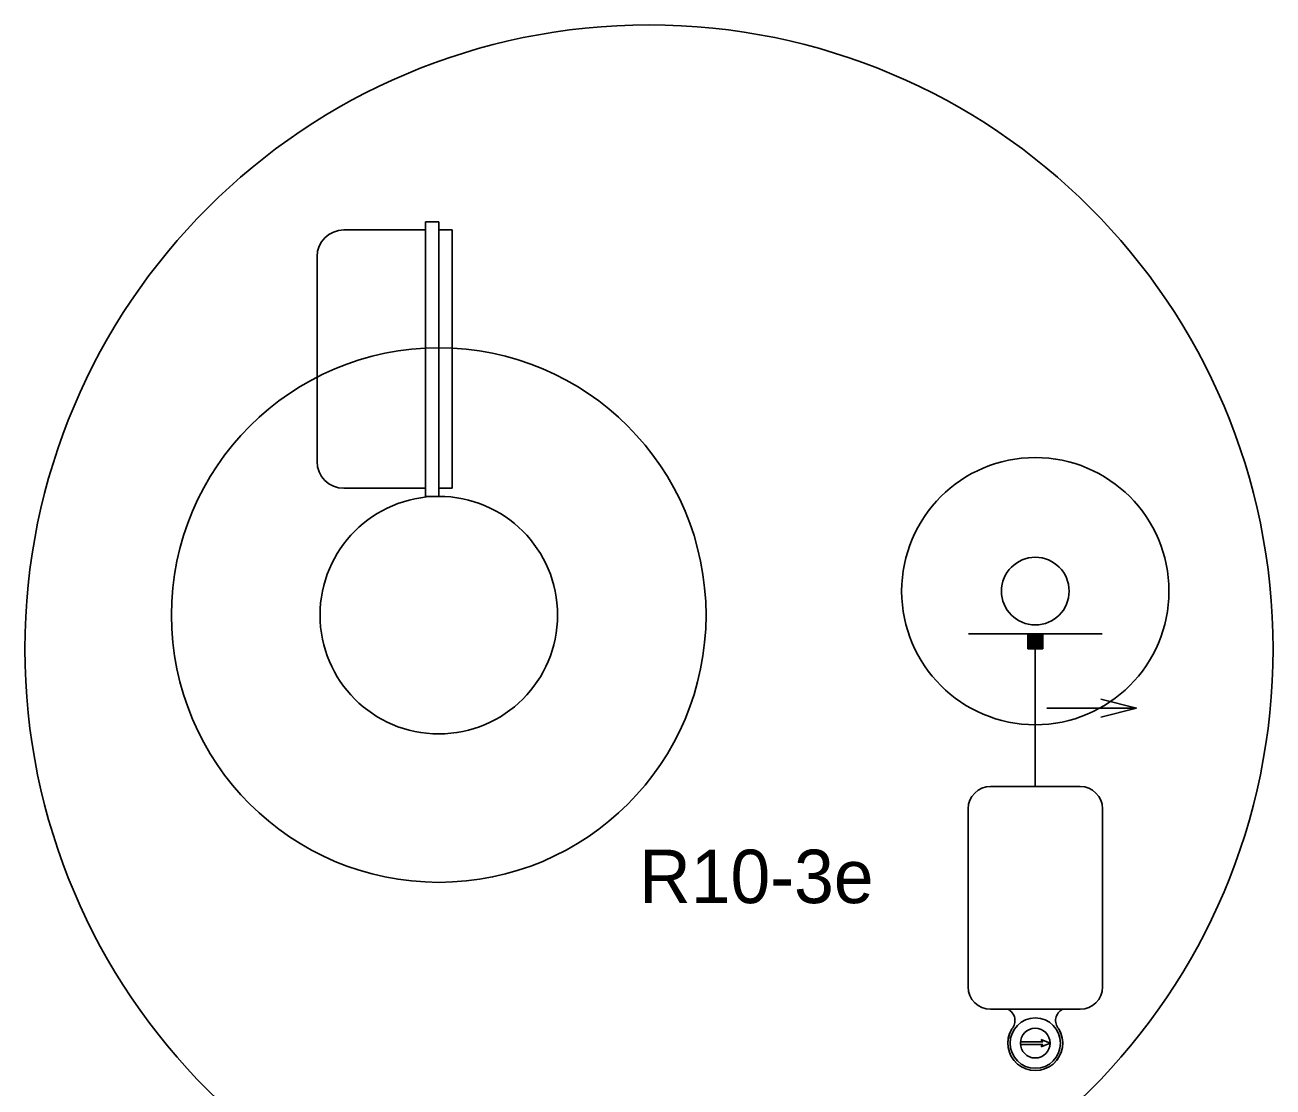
# Model space of a CAD drawing. Extents: x 1369885 to 1370886, y 379976 to 380616.
# Drawn here: x 1370504.6 to 1370609.7, y 380165.8 to 380255.2 of the extents above; entities that cross this region are included whole.
import ezdxf

# ---------------------------------------------------------------- set-up
doc = ezdxf.new("R2010")
doc.units = 0
doc.layers.add('T_Drafting', color=7, linetype='Continuous')

msp = doc.modelspace()

# ---------------------------------------------------------------- linework, layer by layer
at = {"layer": 'T_Drafting'}
for p, q in [((1370538.3, 380215.52), (1370538.3, 380238.64)), ((1370539.43, 380238.64), (1370538.3, 380238.64)), ((1370539.43, 380215.52), (1370539.43, 380238.64)), ((1370538.3, 380237.95), (1370531.43, 380237.95)), ((1370540.55, 380237.95), (1370539.43, 380237.95)), ((1370540.55, 380216.2), (1370540.55, 380237.95)), ((1370529.18, 380218.45), (1370529.18, 380235.7)), ((1370538.3, 380216.2), (1370531.43, 380216.2)), ((1370540.55, 380216.2), (1370539.43, 380216.2)), ((1370539.43, 380215.52), (1370538.3, 380215.52)), ((1370595.28, 380203.94), (1370584.03, 380203.94)), ((1370589.03, 380202.69), (1370589.03, 380203.94)), ((1370589.03, 380202.7), (1370590.27, 380203.94)), ((1370589.03, 380202.72), (1370590.25, 380203.94)), ((1370589.03, 380202.74), (1370590.23, 380203.94)), ((1370589.03, 380202.76), (1370590.21, 380203.94)), ((1370589.03, 380202.78), (1370590.18, 380203.94)), ((1370589.03, 380202.8), (1370590.16, 380203.94)), ((1370589.03, 380202.82), (1370590.14, 380203.94)), ((1370589.03, 380202.84), (1370590.12, 380203.94)), ((1370589.03, 380202.87), (1370590.1, 380203.94)), ((1370589.03, 380202.89), (1370590.08, 380203.94)), ((1370589.03, 380202.91), (1370590.06, 380203.94)), ((1370589.03, 380202.93), (1370590.04, 380203.94)), ((1370589.03, 380202.95), (1370590.01, 380203.94)), ((1370589.03, 380202.97), (1370589.99, 380203.94)), ((1370589.03, 380202.99), (1370589.97, 380203.94)), ((1370589.03, 380203.01), (1370589.95, 380203.94)), ((1370589.03, 380203.04), (1370589.93, 380203.94)), ((1370589.03, 380203.06), (1370589.91, 380203.94)), ((1370589.03, 380203.08), (1370589.89, 380203.94)), ((1370589.03, 380203.1), (1370589.87, 380203.94)), ((1370589.03, 380203.12), (1370589.84, 380203.94)), ((1370589.03, 380203.14), (1370589.82, 380203.94)), ((1370589.03, 380203.16), (1370589.8, 380203.94)), ((1370589.03, 380203.18), (1370589.78, 380203.94)), ((1370589.03, 380203.21), (1370589.76, 380203.94)), ((1370589.03, 380203.23), (1370589.74, 380203.94)), ((1370589.03, 380203.25), (1370589.72, 380203.94)), ((1370589.03, 380203.27), (1370589.7, 380203.94)), ((1370589.03, 380203.29), (1370589.67, 380203.94)), ((1370589.03, 380203.31), (1370589.65, 380203.94)), ((1370589.03, 380203.33), (1370589.63, 380203.94)), ((1370589.03, 380203.35), (1370589.61, 380203.94)), ((1370589.03, 380203.38), (1370589.59, 380203.94)), ((1370589.03, 380203.4), (1370589.57, 380203.94)), ((1370589.03, 380203.42), (1370589.55, 380203.94)), ((1370589.03, 380203.44), (1370589.53, 380203.94)), ((1370589.03, 380203.46), (1370589.51, 380203.94)), ((1370589.03, 380203.48), (1370589.48, 380203.94)), ((1370589.03, 380203.5), (1370589.46, 380203.94)), ((1370589.03, 380203.52), (1370589.44, 380203.94)), ((1370589.03, 380203.54), (1370589.42, 380203.94)), ((1370589.03, 380203.57), (1370589.4, 380203.94)), ((1370589.03, 380203.59), (1370589.38, 380203.94)), ((1370589.03, 380203.61), (1370589.36, 380203.94)), ((1370589.03, 380203.63), (1370589.34, 380203.94)), ((1370589.03, 380203.65), (1370589.31, 380203.94)), ((1370589.03, 380203.67), (1370589.29, 380203.94)), ((1370589.03, 380203.69), (1370589.27, 380203.94)), ((1370589.03, 380203.71), (1370589.25, 380203.94)), ((1370589.03, 380203.74), (1370589.23, 380203.94)), ((1370589.03, 380203.76), (1370589.21, 380203.94)), ((1370589.03, 380203.78), (1370589.19, 380203.94)), ((1370589.03, 380203.8), (1370589.17, 380203.94)), ((1370589.03, 380203.82), (1370589.14, 380203.94)), ((1370589.03, 380203.84), (1370589.12, 380203.94)), ((1370589.03, 380203.86), (1370589.1, 380203.94)), ((1370589.03, 380203.88), (1370589.08, 380203.94)), ((1370589.03, 380203.91), (1370589.06, 380203.94)), ((1370589.03, 380203.93), (1370589.04, 380203.94)), ((1370589.04, 380202.69), (1370590.28, 380203.92)), ((1370589.06, 380202.69), (1370590.28, 380203.9)), ((1370589.08, 380202.69), (1370590.28, 380203.88)), ((1370589.1, 380202.69), (1370590.28, 380203.86)), ((1370589.12, 380202.69), (1370590.28, 380203.84)), ((1370589.15, 380202.69), (1370590.28, 380203.82)), ((1370589.17, 380202.69), (1370590.28, 380203.8)), ((1370589.19, 380202.69), (1370590.28, 380203.78)), ((1370589.21, 380202.69), (1370590.28, 380203.76)), ((1370589.23, 380202.69), (1370590.28, 380203.73)), ((1370589.25, 380202.69), (1370590.28, 380203.71)), ((1370589.27, 380202.69), (1370590.28, 380203.69)), ((1370589.29, 380202.69), (1370590.28, 380203.67)), ((1370589.32, 380202.69), (1370590.28, 380203.65)), ((1370589.34, 380202.69), (1370590.28, 380203.63)), ((1370589.36, 380202.69), (1370590.28, 380203.61)), ((1370589.38, 380202.69), (1370590.28, 380203.59)), ((1370589.4, 380202.69), (1370590.28, 380203.56)), ((1370589.42, 380202.69), (1370590.28, 380203.54)), ((1370589.44, 380202.69), (1370590.28, 380203.52)), ((1370589.46, 380202.69), (1370590.28, 380203.5)), ((1370589.49, 380202.69), (1370590.28, 380203.48)), ((1370589.51, 380202.69), (1370590.28, 380203.46)), ((1370589.53, 380202.69), (1370590.28, 380203.44)), ((1370589.55, 380202.69), (1370590.28, 380203.42)), ((1370589.57, 380202.69), (1370590.28, 380203.39)), ((1370589.59, 380202.69), (1370590.28, 380203.37)), ((1370589.61, 380202.69), (1370590.28, 380203.35)), ((1370590.28, 380202.69), (1370590.28, 380203.94)), ((1370589.03, 380202.69), (1370590.28, 380202.69)), ((1370589.63, 380202.69), (1370590.28, 380203.33)), ((1370589.65, 380202.69), (1370589.65, 380191.08)), ((1370589.66, 380202.69), (1370590.28, 380203.31)), ((1370589.68, 380202.69), (1370590.28, 380203.29)), ((1370589.7, 380202.69), (1370590.28, 380203.27)), ((1370589.72, 380202.69), (1370590.28, 380203.25)), ((1370589.74, 380202.69), (1370590.28, 380203.22)), ((1370589.76, 380202.69), (1370590.28, 380203.2)), ((1370589.78, 380202.69), (1370590.28, 380203.18)), ((1370589.8, 380202.69), (1370590.28, 380203.16)), ((1370589.82, 380202.69), (1370590.28, 380203.14)), ((1370589.85, 380202.69), (1370590.28, 380203.12)), ((1370589.87, 380202.69), (1370590.28, 380203.1)), ((1370589.89, 380202.69), (1370590.28, 380203.08)), ((1370589.91, 380202.69), (1370590.28, 380203.06)), ((1370589.93, 380202.69), (1370590.28, 380203.03)), ((1370589.95, 380202.69), (1370590.28, 380203.01)), ((1370589.97, 380202.69), (1370590.28, 380202.99)), ((1370589.99, 380202.69), (1370590.28, 380202.97)), ((1370590.02, 380202.69), (1370590.28, 380202.95)), ((1370590.04, 380202.69), (1370590.28, 380202.93)), ((1370590.06, 380202.69), (1370590.28, 380202.91)), ((1370590.08, 380202.69), (1370590.28, 380202.89)), ((1370590.1, 380202.69), (1370590.28, 380202.86)), ((1370590.12, 380202.69), (1370590.28, 380202.84)), ((1370590.14, 380202.69), (1370590.28, 380202.82)), ((1370590.16, 380202.69), (1370590.28, 380202.8)), ((1370590.19, 380202.69), (1370590.28, 380202.78)), ((1370590.21, 380202.69), (1370590.28, 380202.76)), ((1370590.23, 380202.69), (1370590.28, 380202.74)), ((1370590.25, 380202.69), (1370590.28, 380202.72)), ((1370590.27, 380202.69), (1370590.28, 380202.69)), ((1370590.62, 380197.69), (1370598.17, 380197.69)), ((1370585.88, 380191.08), (1370593.43, 380191.08)), ((1370584, 380174.21), (1370584, 380189.21)), ((1370595.3, 380189.21), (1370595.3, 380174.21)), ((1370593.43, 380172.33), (1370585.88, 380172.33)), ((1370590.14, 380169.78), (1370590.9, 380169.48)), ((1370590.29, 380169.6), (1370590.14, 380169.78)), ((1370588.41, 380169.6), (1370588.41, 380169.37)), ((1370590.29, 380169.6), (1370588.41, 380169.6)), ((1370590.29, 380169.37), (1370588.41, 380169.37)), ((1370590.14, 380169.18), (1370590.9, 380169.48)), ((1370590.14, 380169.18), (1370590.29, 380169.37))]:
    msp.add_line(p, q, dxfattribs=at)
msp.add_lwpolyline([(1370595.17, 380198.44), (1370598.17, 380197.69), (1370595.17, 380196.94)], dxfattribs=at)
for centre, radius in [((1370557.13, 380202.67), 52.54), ((1370539.43, 380205.52), 22.5), ((1370589.65, 380207.54), 11.25), ((1370539.43, 380205.52), 10), ((1370589.65, 380207.54), 2.85), ((1370589.65, 380169.48), 2.12), ((1370589.65, 380169.48), 1.25)]:
    msp.add_circle(centre, radius, dxfattribs=at)
for centre, radius, start, end in [((1370531.43, 380235.7), 2.25, 90, 180), ((1370531.43, 380218.45), 2.25, 180, 270), ((1370585.88, 380189.21), 1.88, 90, 180), ((1370593.43, 380189.21), 1.88, 0, 90), ((1370585.88, 380174.21), 1.88, 180, 270), ((1370593.43, 380174.21), 1.88, 270, 0), ((1370586.89, 380171.38), 1.05, 318.1972, 64.8044), ((1370592.41, 380171.38), 1.05, 115.1956, 221.8028), ((1370589.65, 380169.48), 2.31, 148.7402, 227.4934), ((1370589.65, 380169.48), 2.31, 148.7402, 31.2598), ((1370589.65, 380169.48), 2.31, 312.5066, 31.2598)]:
    msp.add_arc(centre, radius, start, end, dxfattribs=at)

# ---------------------------------------------------------------- texts
msp.add_text('R10-3e', height=4.5, dxfattribs=at).set_placement((1370556.3, 380181.27))

doc.saveas('drawing.dxf')
